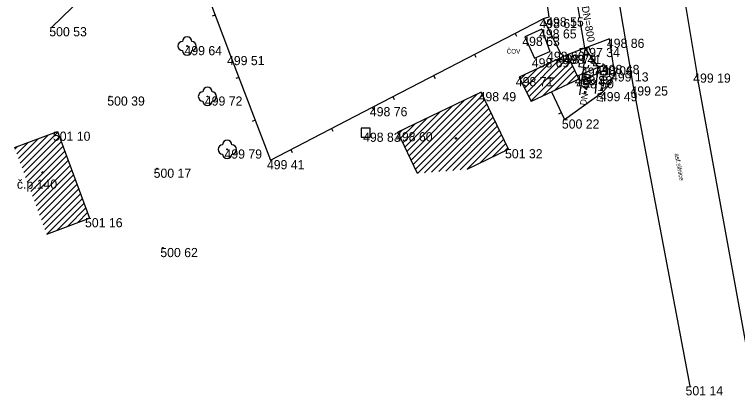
# Model space of a CAD drawing. Extents: x -554123 to -553118, y -1076825 to -1073672.
# Drawn here: x -553505.6 to -553426.8, y -1076809.5 to -1076768 of the extents above; entities that cross this region are included whole.
import ezdxf

# ---------------------------------------------------------------- set-up
doc = ezdxf.new("R2010")
doc.units = 0
for name, color, linetype in [('1', 7, 'Continuous'), ('12', 7, 'Continuous'), ('14', 7, 'Continuous'), ('17', 7, 'Continuous'), ('18', 7, 'Continuous'), ('27', 7, 'Continuous'), ('28', 7, 'Continuous'), ('32', 7, 'Continuous'), ('34', 7, 'Continuous'), ('40', 7, 'Continuous'), ('47', 7, 'Continuous'), ('49', 7, 'Continuous'), ('50', 7, 'Continuous'), ('52', 7, 'Continuous'), ('54', 7, 'Continuous'), ('6', 7, 'Continuous')]:
    doc.layers.add(name, color=color, linetype=linetype)

# ---------------------------------------------------------------- blocks, each defined once
blk = doc.blocks.new('POINT_DISPLAY')
blk.add_line((0, 0), (0, 0))
blk = doc.blocks.new('JS800')
at = {"layer": '49'}
blk.add_text('DN=800', height=0.8, rotation=359.99988, dxfattribs=at).set_placement((0, 0))
blk = doc.blocks.new('JS400')
at = {"layer": '49'}
for p, q in [((1.852, 0.799), (1.853, 0)), ((1.1, 0.435), (1.346, 0.434)), ((1.101, 0.303), (1.346, 0.303))]:
    blk.add_line(p, q, dxfattribs=at)
for points in [[(1.852, 0.799), (1.569, 0.265), (1.999, 0.265)], [(2.358, 0.8), (2.273, 0.763), (2.215, 0.642), (2.187, 0.454), (2.188, 0.34), (2.216, 0.151), (2.272, 0.038), (2.357, -0.001), (2.415, 0), (2.5, 0.038), (2.56, 0.151), (2.589, 0.341), (2.588, 0.453), (2.561, 0.642), (2.5, 0.763), (2.414, 0.8), (2.358, 0.8)], [(2.952, 0.8), (2.868, 0.762), (2.81, 0.643), (2.783, 0.454), (2.782, 0.34), (2.811, 0.152), (2.868, 0.038), (2.952, 0), (3.009, 0), (3.094, 0.038), (3.156, 0.152), (3.183, 0.341), (3.184, 0.454), (3.155, 0.643), (3.094, 0.763), (3.01, 0.799), (2.952, 0.8)]]:
    blk.add_lwpolyline(points, dxfattribs=at)
blk.add_text('DN', height=0.7, dxfattribs=at).set_placement((-0.2, 0.074))
blk = doc.blocks.new('SA')
at = {"layer": '50'}
blk.add_lwpolyline([(-0.5, -0.5), (0.5, -0.5), (0.5, 0.5), (-0.5, 0.5)], close=True, dxfattribs=at)
blk = doc.blocks.new('T')
at = {"layer": '6'}
blk.add_circle((0, 0), 0.05, dxfattribs=at)
blk = doc.blocks.new('STL')
at = {"layer": '34'}
blk.add_circle((0, 0), 0.05, dxfattribs=at)
for centre, start, end in [((0, 0.5), 0, 180), ((-0.5, 0), 90, 270), ((0.5, 0), 270, 90), ((0, -0.5), 180, 0)]:
    blk.add_arc(centre, 0.5, start, end, dxfattribs=at)
blk = doc.blocks.new('VYUST')
at = {"layer": '40'}
for p, q in [((-0.35, 0.501), (0, 0.5)), ((0, 0.5), (0, -0.5)), ((0, 0), (3, 0)), ((-0.35, -0.5), (0, -0.5))]:
    blk.add_line(p, q, dxfattribs=at)
blk = doc.blocks.new('BN')
at = {"layer": '47'}
blk.add_line((-0.25, 0), (0.25, 0), dxfattribs=at)
blk = doc.blocks.new('BZ')
at = {"layer": '47'}
blk.add_circle((0, 0), 0.0875, dxfattribs=at)

msp = doc.modelspace()

# ---------------------------------------------------------------- linework, layer by layer
at = {"layer": '12'}
for p, q in [((-553450.54, -1076744.62), (-553447.37, -1076768.32)), ((-553501.52, -1076769.39), (-553488.17, -1076756.39)), ((-553488.17, -1076756.39), (-553482.04, -1076772.53)), ((-553483.732, -1076768.076), (-553484.059, -1076768.2)), ((-553466.58, -1076778.1), (-553447.99, -1076768.5)), ((-553447.37, -1076768.32), (-553447.99, -1076768.5)), ((-553447.99, -1076768.5), (-553446.01, -1076772.37)), ((-553451.031, -1076770.07), (-553450.87, -1076770.381)), ((-553455.473, -1076772.365), (-553455.313, -1076772.676)), ((-553482.04, -1076772.53), (-553477.7, -1076783.87)), ((-553459.916, -1076774.659), (-553459.756, -1076774.97)), ((-553481.146, -1076774.865), (-553481.473, -1076774.99)), ((-553464.359, -1076776.953), (-553464.198, -1076777.264)), ((-553447.056, -1076776.44), (-553445.66, -1076779.44)), ((-553477.7, -1076783.87), (-553466.58, -1076778.1)), ((-553466.605, -1076778.113), (-553466.444, -1076778.423)), ((-553446.001, -1076778.707), (-553446.319, -1076778.854)), ((-553479.359, -1076779.535), (-553479.686, -1076779.66)), ((-553471.043, -1076780.416), (-553470.882, -1076780.726)), ((-553475.481, -1076782.719), (-553475.32, -1076783.029))]:
    msp.add_line(p, q, dxfattribs=at)
at = {"layer": '14'}
for p, q in [((-553445.38, -1076772.41), (-553450.58, -1076774.83)), ((-553445.38, -1076772.41), (-553444.09, -1076775.06)), ((-553450.58, -1076774.83), (-553449.29, -1076777.48)), ((-553444.09, -1076775.06), (-553449.29, -1076777.48)), ((-553454.74, -1076776.47), (-553463.83, -1076780.83)), ((-553451.75, -1076782.68), (-553454.74, -1076776.47)), ((-553505.595, -1076782.516), (-553500.91, -1076780.77)), ((-553500.91, -1076780.77), (-553497.4, -1076790.19)), ((-553461.668, -1076785.338), (-553463.83, -1076780.83)), ((-553456.255, -1076784.849), (-553451.75, -1076782.68)), ((-553502.085, -1076791.936), (-553497.4, -1076790.19))]:
    msp.add_line(p, q, dxfattribs=at)
at = {"layer": '17'}
for p, q in [((-553441.16, -1076758.15), (-553438.18, -1076775.84)), ((-553434.09, -1076757.5), (-553431.22, -1076774.44)), ((-553425.47, -1076806.18), (-553431.22, -1076774.44)), ((-553438.18, -1076775.84), (-553431.98, -1076808.5))]:
    msp.add_line(p, q, dxfattribs=at)
at = {"layer": '18'}
for p, q in [((-553448.14, -1076769.62), (-553449.97, -1076770.44)), ((-553448.14, -1076769.62), (-553447.26, -1076772.06)), ((-553449.97, -1076770.44), (-553448.92, -1076772.78)), ((-553448.92, -1076772.78), (-553447.26, -1076772.06)), ((-553441.31, -1076773.5), (-553444.26, -1076774.72)), ((-553441.31, -1076773.5), (-553441.08, -1076774.054)), ((-553441.08, -1076774.054), (-553444.03, -1076775.274)), ((-553444.09, -1076775.06), (-553444.03, -1076775.274))]:
    msp.add_line(p, q, dxfattribs=at)
at = {"layer": '27'}
for p, q in [((-553440.75, -1076770.65), (-553445.38, -1076772.41)), ((-553440.19, -1076774.31), (-553440.75, -1076770.65)), ((-553445.66, -1076779.44), (-553441.51, -1076776.46))]:
    msp.add_line(p, q, dxfattribs=at)
msp.add_lwpolyline([(-553441.51, -1076776.46), (-553441.013, -1076775.928), (-553440.682, -1076775.423), (-553440.368, -1076774.865), (-553440.19, -1076774.31)], dxfattribs=at)
at = {"layer": '28'}
for p, q in [((-553443.45, -1076771.65), (-553443.6, -1076773.79)), ((-553442.01, -1076773.65), (-553443.45, -1076771.65))]:
    msp.add_line(p, q, dxfattribs=at)
at = {"layer": '32'}
for p, q in [((-553449.769, -1076776.496), (-553445.946, -1076772.673)), ((-553449.537, -1076776.972), (-553445.248, -1076772.682)), ((-553449.306, -1076777.447), (-553445.016, -1076773.158)), ((-553450.232, -1076775.545), (-553448.591, -1076773.905)), ((-553450, -1076776.021), (-553447.269, -1076773.289)), ((-553448.058, -1076776.907), (-553444.785, -1076773.633)), ((-553450.463, -1076775.069), (-553449.914, -1076774.52)), ((-553446.735, -1076776.291), (-553444.553, -1076774.109)), ((-553445.413, -1076775.676), (-553444.322, -1076774.584)), ((-553462.364, -1076783.887), (-553455.138, -1076776.661)), ((-553462.135, -1076784.365), (-553454.577, -1076776.808)), ((-553462.822, -1076782.931), (-553457.856, -1076777.964)), ((-553462.593, -1076783.409), (-553456.497, -1076777.313)), ((-553461.906, -1076784.843), (-553454.348, -1076777.285)), ((-553461.676, -1076785.321), (-553454.118, -1076777.762)), ((-553463.052, -1076782.453), (-553459.215, -1076778.616)), ((-553460.919, -1076785.27), (-553453.888, -1076778.239)), ((-553460.142, -1076785.2), (-553453.658, -1076778.717)), ((-553463.281, -1076781.975), (-553460.574, -1076779.268)), ((-553459.364, -1076785.13), (-553453.428, -1076779.194)), ((-553463.51, -1076781.497), (-553461.932, -1076779.92)), ((-553458.587, -1076785.06), (-553453.199, -1076779.671)), ((-553457.81, -1076784.989), (-553452.969, -1076780.149)), ((-553504.772, -1076784.724), (-553500.885, -1076780.837)), ((-553463.739, -1076781.019), (-553463.291, -1076780.572)), ((-553457.032, -1076784.919), (-553452.739, -1076780.626)), ((-553456.255, -1076784.849), (-553452.509, -1076781.103)), ((-553505.156, -1076783.694), (-553503.019, -1076781.556)), ((-553504.964, -1076784.209), (-553501.891, -1076781.136)), ((-553504.58, -1076785.239), (-553500.693, -1076781.352)), ((-553504.388, -1076785.754), (-553500.501, -1076781.867)), ((-553454.891, -1076784.192), (-553452.279, -1076781.58)), ((-553505.54, -1076782.663), (-553505.273, -1076782.396)), ((-553505.348, -1076783.178), (-553504.146, -1076781.976)), ((-553504.196, -1076786.269), (-553500.309, -1076782.382)), ((-553453.528, -1076783.536), (-553452.05, -1076782.058)), ((-553452.164, -1076782.879), (-553451.82, -1076782.535)), ((-553504.005, -1076786.784), (-553500.117, -1076782.897)), ((-553503.813, -1076787.3), (-553499.925, -1076783.412)), ((-553503.621, -1076787.815), (-553499.733, -1076783.928)), ((-553503.429, -1076788.33), (-553499.541, -1076784.443)), ((-553503.237, -1076788.845), (-553499.35, -1076784.958)), ((-553503.045, -1076789.36), (-553499.158, -1076785.473)), ((-553502.853, -1076789.875), (-553498.966, -1076785.988)), ((-553502.661, -1076790.391), (-553498.774, -1076786.503)), ((-553502.469, -1076790.906), (-553498.582, -1076787.019)), ((-553502.277, -1076791.421), (-553498.39, -1076787.534)), ((-553502.085, -1076791.936), (-553498.198, -1076788.049)), ((-553500.958, -1076791.516), (-553498.006, -1076788.564)), ((-553499.831, -1076791.096), (-553497.814, -1076789.079)), ((-553498.703, -1076790.676), (-553497.622, -1076789.594)), ((-553497.576, -1076790.256), (-553497.43, -1076790.109))]:
    msp.add_line(p, q, dxfattribs=at)

# ---------------------------------------------------------------- block references
at = {"layer": '1'}
for p in [(-553447.99, -1076768.5), (-553447.37, -1076768.32), (-553501.52, -1076769.39), (-553448.14, -1076769.62), (-553449.97, -1076770.44), (-553440.75, -1076770.65), (-553486.78, -1076771.45), (-553443.45, -1076771.65), (-553443.45, -1076771.65), (-553447.26, -1076772.06), (-553446.01, -1076772.37), (-553445.38, -1076772.41), (-553482.04, -1076772.53), (-553448.92, -1076772.78), (-553443.6, -1076773.79), (-553443.6, -1076773.79), (-553442.01, -1076773.65), (-553441.31, -1076773.5), (-553444.26, -1076774.72), (-553440.19, -1076774.31), (-553431.22, -1076774.44), (-553450.58, -1076774.83), (-553444.09, -1076775.06), (-553438.18, -1076775.84), (-553495.19, -1076776.94), (-553484.56, -1076776.94), (-553454.74, -1076776.47), (-553441.51, -1076776.46), (-553466.58, -1076778.1), (-553445.66, -1076779.44), (-553500.91, -1076780.77), (-553467.33, -1076780.88), (-553463.83, -1076780.83), (-553451.75, -1076782.68), (-553482.41, -1076782.71), (-553477.7, -1076783.87), (-553490.04, -1076784.8), (-553497.4, -1076790.19), (-553489.41, -1076793.44), (-553431.98, -1076808.5)]:
    msp.add_blockref('POINT_DISPLAY', p, dxfattribs=at)
at = {"layer": '32'}
for p in [(-553456.255, -1076784.849), (-553502.085, -1076791.936)]:
    msp.add_blockref('POINT_DISPLAY', p, dxfattribs=at)
at = {"layer": '34'}
for p in [(-553486.78, -1076771.45), (-553484.56, -1076776.94), (-553482.41, -1076782.71)]:
    msp.add_blockref('STL', p, dxfattribs=at)
at = {"layer": '40'}
for p, xscale, yscale, rotation in [((-553444.51, -1076765.39), 1.000000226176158, 1.000000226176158, -80.38924721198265), ((-553443.45, -1076771.65), 1.000000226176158, 1.000000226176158, 99.61075278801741), ((-553443.6, -1076773.79), 0.9999995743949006, 0.9999995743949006, -98.1198770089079), ((-553442.01, -1076773.65), 1.0000003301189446, 1.0000003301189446, -96.09033926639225)]:
    msp.add_blockref('VYUST', p, dxfattribs=dict(at, xscale=xscale, yscale=yscale, rotation=rotation))
at = {"layer": '47'}
for name, p in [('BN', (-553447.104, -1076774.911)), ('BZ', (-553457.473, -1076781.509)), ('BZ', (-553502.515, -1076785.219))]:
    msp.add_blockref(name, p, dxfattribs=at)
at = {"layer": '49'}
for name, p, xscale, yscale, rotation in [('JS800', (-553443.788, -1076767.17), 0.9999985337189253, 0.9999985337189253, -80.2438855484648), ('JS400', (-553443.187, -1076777.765), 0.9999974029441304, 0.9999974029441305, 81.63531725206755), ('JS400', (-553441.384, -1076777.395), 0.9999974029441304, 0.9999974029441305, 81.63531725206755)]:
    msp.add_blockref(name, p, dxfattribs=dict(at, xscale=xscale, yscale=yscale, rotation=rotation))
at = {"layer": '50'}
msp.add_blockref('SA', (-553467.33, -1076780.88), dxfattribs=at)
at = {"layer": '6'}
for p in [(-553495.19, -1076776.94), (-553490.04, -1076784.8), (-553489.41, -1076793.44)]:
    msp.add_blockref('T', p, dxfattribs=at)

# ---------------------------------------------------------------- texts
at = {"layer": '52'}
msp.add_text('ČOV', height=0.5, dxfattribs=at).set_placement((-553451.961, -1076772.269))
msp.add_text('asf.silnice', height=0.5, rotation=280.74882, dxfattribs=at).set_placement((-553433.665, -1076783.176))
at = {"layer": '54'}
msp.add_text('č.p.140', height=1, dxfattribs=at).set_placement((-553505.331, -1076786.992))
at = {"layer": '6'}
for s, p in [('498 61 ', (-553448.383, -1076769.5)), ('498 55 ', (-553447.644, -1076769.32)), ('500 53 ', (-553501.798, -1076770.39)), ('498 65 ', (-553448.426, -1076770.62)), ('498 63 ', (-553450.256, -1076771.44)), ('498 86 ', (-553441.036, -1076771.65)), ('499 64 ', (-553487.066, -1076772.45)), ('497 34 ', (-553443.71, -1076772.65)), ('497 34 ', (-553443.71, -1076772.65)), ('498 66 ', (-553447.558, -1076773.06)), ('498 79 ', (-553446.294, -1076773.37)), ('498 41 ', (-553445.749, -1076773.41)), ('499 51 ', (-553482.433, -1076773.53)), ('498 69 ', (-553449.218, -1076773.78)), ('497 47 ', (-553443.858, -1076774.79)), ('497 47 ', (-553443.858, -1076774.79)), ('498 06 ', (-553442.298, -1076774.65)), ('498 48 ', (-553441.572, -1076774.5)), ('498 71 ', (-553450.959, -1076775.83)), ('498 48 ', (-553444.522, -1076775.72)), ('499 13 ', (-553440.585, -1076775.31)), ('499 19 ', (-553431.627, -1076775.44)), ('498 50 ', (-553444.366, -1076776.06)), ('499 25 ', (-553438.466, -1076776.84)), ('500 39 ', (-553495.48, -1076777.94)), ('499 72 ', (-553484.844, -1076777.94)), ('498 49 ', (-553455.014, -1076777.47)), ('499 49 ', (-553441.796, -1076777.46)), ('498 76 ', (-553466.864, -1076779.1)), ('500 22 ', (-553445.938, -1076780.44)), ('501 10 ', (-553501.406, -1076781.77)), ('498 83 ', (-553467.604, -1076781.88)), ('498 60 ', (-553464.118, -1076781.83)), ('499 79 ', (-553482.706, -1076783.71)), ('501 32 ', (-553452.135, -1076783.68)), ('499 41 ', (-553478.081, -1076784.87)), ('500 17 ', (-553490.425, -1076785.8)), ('501 16 ', (-553497.906, -1076791.19)), ('500 62 ', (-553489.7, -1076794.44)), ('501 14 ', (-553432.462, -1076809.5))]:
    msp.add_text(s, height=1, dxfattribs=at).set_placement(p)

doc.saveas('drawing.dxf')
